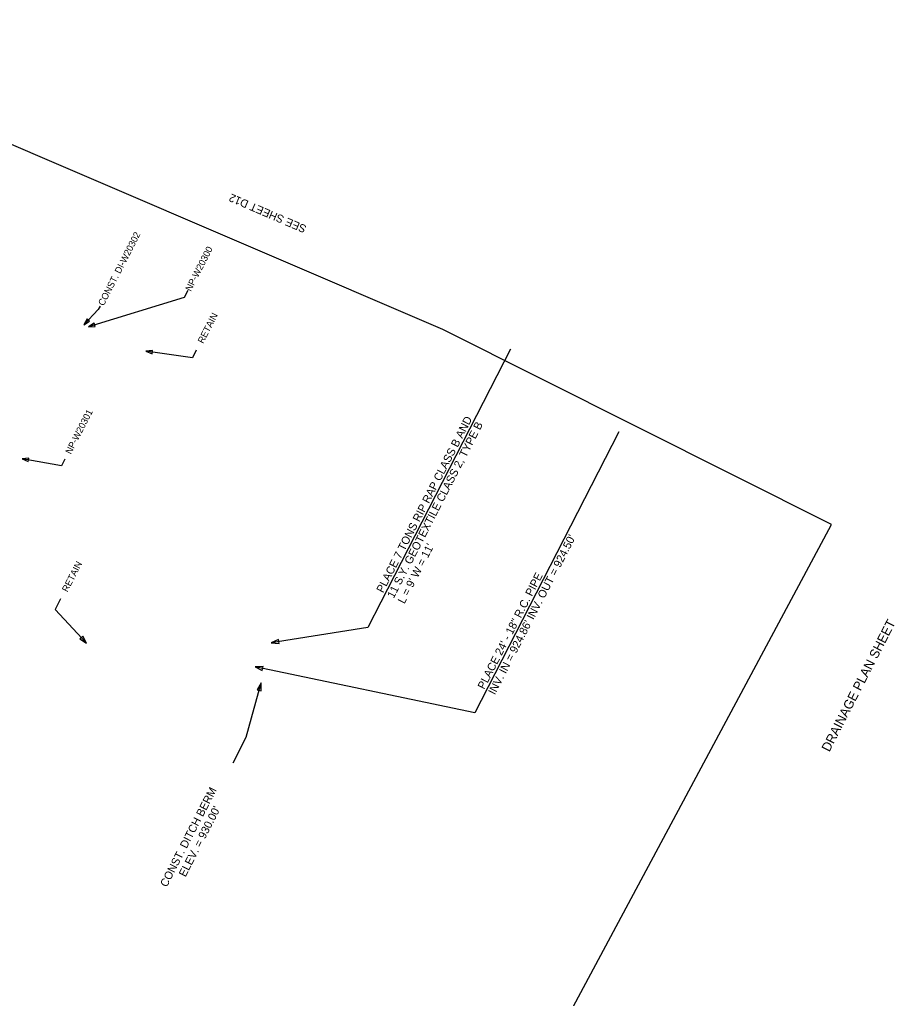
# Model space of a CAD drawing. Extents: x 1614575 to 1616117, y 1096819 to 1098677.
# Drawn here: x 1615461 to 1616117, y 1097888 to 1098622 of the extents above; entities that cross this region are included whole.
import ezdxf

# ---------------------------------------------------------------- set-up
doc = ezdxf.new("R2010")
doc.units = 0
for name, color, linetype in [('Level 12', 7, 'Continuous'), ('Level 19', 7, 'Continuous'), ('Level 8', 7, 'Continuous'), ('RD_HC_Data_Tic', 7, 'Continuous')]:
    doc.layers.add(name, color=color, linetype=linetype)

msp = doc.modelspace()

# ---------------------------------------------------------------- linework, layer by layer
at = {"layer": 'Level 19'}
msp.add_lwpolyline([(1614788.78, 1097308.44), (1614938.71, 1097183.17), (1614915.33, 1097153.87), (1614985.17, 1097098.15), (1614971.19, 1097080.18), (1615113.55, 1096967.95), (1615306.49, 1096819.15), (1616070.13, 1098243.47), (1615778.49, 1098389.73), (1615502.74, 1098507.9), (1615236.09, 1098622.18), (1615164.05, 1098481.19), (1615133.61, 1098496.74), (1614575.12, 1097403.7), (1614683.85, 1097348.14)], close=True, dxfattribs=at)
msp.add_lwpolyline([(1614788.78, 1097308.44), (1614938.71, 1097183.17), (1614915.33, 1097153.87), (1614985.17, 1097098.15), (1614971.19, 1097080.18), (1615113.55, 1096967.95), (1615306.49, 1096819.15), (1616070.13, 1098243.47), (1615778.49, 1098389.73), (1615502.74, 1098507.9), (1615236.09, 1098622.18), (1615164.05, 1098481.19), (1615133.61, 1098496.74), (1614575.12, 1097403.7), (1614683.85, 1097348.14)], close=True, dxfattribs=at)
msp.add_lwpolyline([(1614788.78, 1097308.44), (1614938.71, 1097183.17), (1614915.33, 1097153.87), (1614985.17, 1097098.15), (1614971.19, 1097080.18), (1615113.55, 1096967.95), (1615306.49, 1096819.15), (1616070.13, 1098243.47), (1615778.49, 1098389.73), (1615502.74, 1098507.9), (1615236.09, 1098622.18), (1615164.05, 1098481.19), (1615133.61, 1098496.74), (1614575.12, 1097403.7), (1614683.85, 1097348.14)], close=True, dxfattribs=at)
msp.add_lwpolyline([(1614788.78, 1097308.44), (1614938.71, 1097183.17), (1614915.33, 1097153.87), (1614985.17, 1097098.15), (1614971.19, 1097080.18), (1615113.55, 1096967.95), (1615306.49, 1096819.15), (1616070.13, 1098243.47), (1615778.49, 1098389.73), (1615502.74, 1098507.9), (1615236.09, 1098622.18), (1615164.05, 1098481.19), (1615133.61, 1098496.74), (1614575.12, 1097403.7), (1614683.85, 1097348.14)], close=True, dxfattribs=at)
msp.add_lwpolyline([(1614788.78, 1097308.44), (1614938.71, 1097183.17), (1614915.33, 1097153.87), (1614985.17, 1097098.15), (1614971.19, 1097080.18), (1615113.55, 1096967.95), (1615306.49, 1096819.15), (1616070.13, 1098243.47), (1615778.49, 1098389.73), (1615502.74, 1098507.9), (1615236.09, 1098622.18), (1615164.05, 1098481.19), (1615133.61, 1098496.74), (1614575.12, 1097403.7), (1614683.85, 1097348.14)], close=True, dxfattribs=at)
at = {"layer": 'Level 8'}
for p, q in [((1615829.2, 1098375.07), (1615731.99, 1098185.4)), ((1615910.42, 1098313.06), (1615807.2, 1098111.64))]:
    msp.add_line(p, q, dxfattribs=at)
for points in [[(1615587.21, 1098419.14), (1615584.43, 1098413.71), (1615512.63, 1098391.82)], [(1615521.33, 1098407.31), (1615519.98, 1098404.68), (1615509.18, 1098393.29)], [(1615593.52, 1098374.26), (1615590.59, 1098368.53), (1615555.77, 1098373.51)], [(1615494.91, 1098292.49), (1615492.32, 1098287.45), (1615462.83, 1098292.83)], [(1615491.73, 1098187.87), (1615487.6, 1098179.82), (1615511.14, 1098154.6)], [(1615731.99, 1098185.4), (1615722.26, 1098166.41), (1615649.66, 1098154.79)], [(1615807.2, 1098111.64), (1615802.36, 1098102.21), (1615637.59, 1098136.75)], [(1615621.06, 1098064.81), (1615630.98, 1098084.18), (1615642.23, 1098124.77)]]:
    msp.add_lwpolyline(points, dxfattribs=at)
for points in [[(1615511.56, 1098397.69), (1615509.18, 1098393.29), (1615513.44, 1098395.91)], [(1615516.87, 1098394.47), (1615512.63, 1098391.82), (1615517.63, 1098391.99)], [(1615560.74, 1098374.11), (1615555.77, 1098373.51), (1615560.37, 1098371.55)], [(1615467.81, 1098293.24), (1615462.83, 1098292.83), (1615467.35, 1098290.69)], [(1615506.05, 1098157.78), (1615511.14, 1098154.6), (1615508.32, 1098159.9)], [(1615655.13, 1098157.24), (1615649.66, 1098154.79), (1615655.63, 1098154.18)], [(1615643.58, 1098137.08), (1615637.59, 1098136.75), (1615642.94, 1098134.04)], [(1615642.18, 1098118.77), (1615642.23, 1098124.77), (1615639.19, 1098119.6)]]:
    msp.add_lwpolyline(points, close=True, dxfattribs=at)

# ---------------------------------------------------------------- texts
at = {"layer": 'Level 12'}
msp.add_text('DRAINAGE PLAN SHEET', height=6.9833, rotation=62.86504, dxfattribs=at).set_placement((1616068.39, 1098072.54))
at = {"layer": 'Level 8'}
for s, height, p in [('CONST. DI-W20302', 5, (1615524.01, 1098407.06)), ('NP-W20300', 5, (1615589.44, 1098418)), ('RETAIN', 5, (1615598.69, 1098378.86)), ('NP-W20301', 5, (1615499.41, 1098295.8)), ('PLACE 7 TONS RIP RAP CLASS B AND', 6, (1615733.6, 1098191.83)), ('11 S.Y. GEOTEXTILE CLASS 2, TYPE B', 6, (1615741.61, 1098187.72)), ("INV. IN = 924.86' INV. OUT = 924.50'", 6, (1615817.52, 1098115.34)), ("L = 9' W = 11'", 6, (1615749.62, 1098183.62)), ('RETAIN', 5, (1615496.89, 1098192.47)), ('PLACE 24\' - 18" R.C. PIPE', 6, (1615809.51, 1098119.44)), ('CONST. DITCH BERM', 6, (1615571.38, 1097971.17)), ("ELEV. = 930.00'", 6, (1615585.4, 1097978.79))]:
    msp.add_text(s, height=height, rotation=62.86504, dxfattribs=at).set_placement(p)
at = {"layer": 'RD_HC_Data_Tic'}
msp.add_text('SEE SHEET D12', height=6, rotation=156.80236, dxfattribs=at).set_placement((1615676.71, 1098467.41))

doc.saveas('drawing.dxf')
